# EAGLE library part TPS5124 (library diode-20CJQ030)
Ti's TPS5124 dual channel, synchronous step-down PWM controller Description: The TPS5124 is dual independent high efficiency synchronous step-down controller. It supports a low-voltage/high-current power supply applications that use either a 5-V or 12-V bus voltage. Since both controllers of the TPS5124 operate 180 degree out-of-phase, the input current ripple is minimized resulting in a smaller input capacitance and reduced power supply cost. The current protection circuit detects the drain-to-source voltage drop across the high-side and low-side power MOSFET while it is conducting. Also, the current protection circuit has a temperature coefficient to compensate for the RDS(on) variation of the MOSFET. This resistor-less current protection and built-in boost diode simplify the system design and reduces the external parts count. Other features such as undervoltage lockout, overvoltage, undervoltage, and programmable short-circuit protection promote system reliability. Features: High Efficiency - No Current Sense Resistor Required, RDS(on) Overcurrent Detection with Temperature Compensation Adjustable Output Voltage Down to 0.9 V Voltage-Mode PWM Control: Maximum 500-kHz Operation 180° Out-of-Phase Control Individual Standby and Soft-Start for Each Channel - Easy Power Sequencing Overvoltage and Undervoltage Protection Built-In Boot-Strap Diode Built-In 5-V Linear Regulator Accurate ± 1% 0.85-V Reference Applications: Consumer Game Systems DSP Applications Digital Set-Top Box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
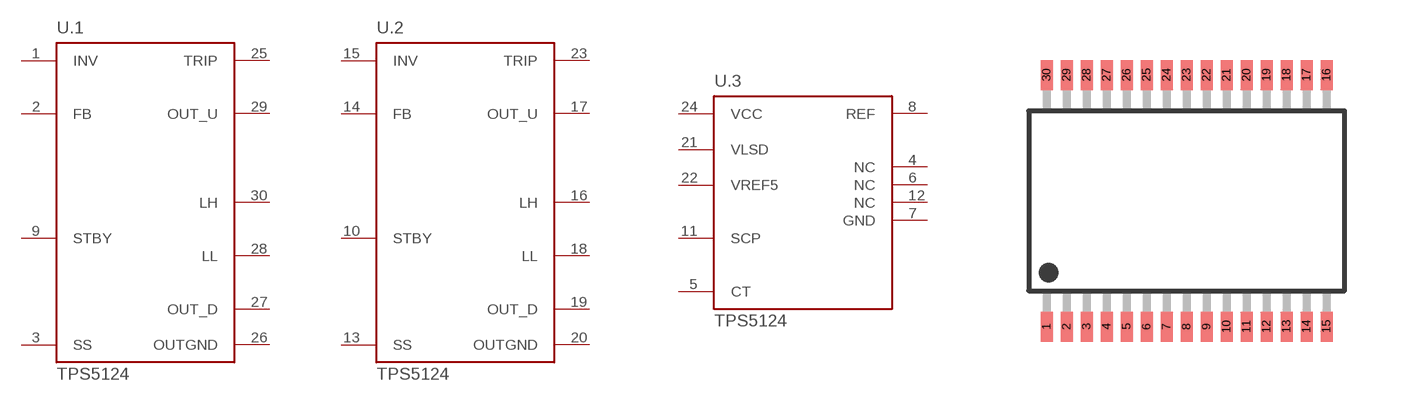
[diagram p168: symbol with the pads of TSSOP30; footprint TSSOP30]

Designator prefix U; gates .1=TPS5124 .2=TPS5124 .3=TPS5124_PWR

## TPS5124  [TSSOP30]
1  .1:INV  in
2  .1:FB  in
3  .1:SS  in
4  .3:NC  nc
5  .3:CT
6  .3:NC  nc
7  .3:GND  pwr
8  .3:REF  out
9  .1:STBY  in
10  .2:STBY  in
11  .3:SCP
12  .3:NC  nc
13  .2:SS  in
14  .2:FB  in
15  .2:INV  in
16  .2:LH  in
17  .2:OUT_U  out
18  .2:LL
19  .2:OUT_D  out
20  .2:OUTGND  out
21  .3:VLSD  pwr
22  .3:VREF5  out
23  .2:TRIP  in
24  .3:VCC  pwr
25  .1:TRIP  in
26  .1:OUTGND  out
27  .1:OUT_D  out
28  .1:LL
29  .1:OUT_U  out
30  .1:LH  in

## Footprint TSSOP30 (pad centres in mm)
smd 0.3 x 0.75: 1 -3.5,-3.15; 2 -3,-3.15; 3 -2.5,-3.15; 4 -2,-3.15; 5 -1.5,-3.15; 6 -1,-3.15; 7 -0.5,-3.15; 8 0,-3.15; 9 0.5,-3.15; 10 1,-3.15; 11 1.5,-3.15; 12 2,-3.15; 13 2.5,-3.15; 14 3,-3.15; 15 3.5,-3.15; 16 3.5,3.15; 17 3,3.15; 18 2.5,3.15; 19 2,3.15; 20 1.5,3.15; 21 1,3.15; 22 0.5,3.15; 23 0,3.15; 24 -0.5,3.15; 25 -1,3.15; 26 -1.5,3.15; 27 -2,3.15; 28 -2.5,3.15; 29 -3,3.15; 30 -3.5,3.15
